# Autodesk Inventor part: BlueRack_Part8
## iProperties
Shininess: 64.0
Length Units: 11272
Angle Units: 11279
Time Units: 11290
Mass Units: 11286
Length Display Precision: 3
Angle Display Precision: 2
Compacted: True
Part Number: BlueRack_Part8
Document SubType Name: Modeling
Created: 2004-12
Designer: John Blackburn
Material: Steel, Mild
Manufacturer: Standard
Standards Organization: Custom
Density: 0.0
Volumn: 0.0
Area: 0.0
PropertySet Name: Model Information
Control State: 0
Master: False
Checked Out: False
Author: John Blackburn
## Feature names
1. Extrusion1
2. Extrusion2
3. Extrusion3
4. Extrusion4
5. Extrusion5
6. Fillet1
7. Fillet2
8. Extrusion6
9. Extrusion7
